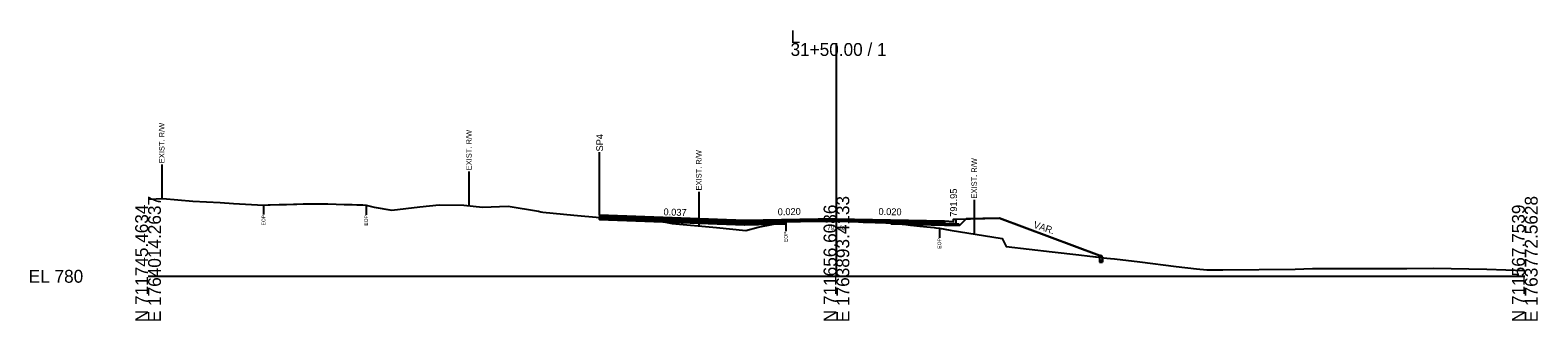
# Model space of a CAD drawing. Extents: x -26 to 5303, y -10 to 9578.
# Drawn here: x 1974.3 to 2302.8, y 1490.3 to 1553.6 of the extents above; entities that cross this region are included whole.
import ezdxf

# ---------------------------------------------------------------- set-up
doc = ezdxf.new("R2010")
doc.units = 0
for name, color, linetype in [('Default', 7, 'Continuous'), ('Exist CMT Pavement', 7, 'Continuous'), ('Exist Cross Section Cell', 7, 'Continuous'), ('Exist XS Ground Line', 7, 'Continuous'), ('Old_Level_10', 7, 'Continuous'), ('Old_Level_3', 7, 'Continuous'), ('Prop CMT Conc Surface', 7, 'Continuous'), ('Prop CMT Concrete Structures', 7, 'Continuous'), ('Prop CMT Pvmt Course 1', 7, 'Continuous'), ('Prop CMT Pvmt Course 1 CG', 7, 'Continuous'), ('Prop CMT Pvmt Course 2', 7, 'Continuous'), ('Prop CMT Pvmt Course 3', 7, 'Continuous'), ('Prop CMT Pvmt Surface', 7, 'Continuous'), ('Prop CMT Slope Grass', 7, 'Continuous'), ('Prop CMT Subgrade Earthwork', 7, 'Continuous'), ('Prop XS Earthwork Shape', 7, 'Continuous'), ('Prop XS Hydro Elevations', 7, 'Continuous'), ('Prop XS SE Text', 7, 'Continuous'), ('Prop XS Shear Point Element', 7, 'Continuous'), ('Prop XS Side Slope Text', 7, 'Continuous'), ('Prop XS Wedging', 7, 'Continuous'), ('Typical Curb CELL', 7, 'Continuous')]:
    doc.layers.add(name, color=color, linetype=linetype)

msp = doc.modelspace()

# ---------------------------------------------------------------- linework, layer by layer
at = {"layer": 'Exist CMT Pavement'}
msp.add_lwpolyline([(2138.95, 1511.9), (2140.27, 1511.94), (2141.07, 1511.96), (2142.16, 1511.96), (2142.86, 1511.97), (2143.38, 1511.98), (2144.65, 1512), (2146.74, 1512), (2149.58, 1512.03), (2150, 1512.02), (2150.74, 1512.02), (2152.68, 1511.94), (2153.59, 1511.9), (2154.83, 1511.85), (2155.38, 1511.83), (2155.79, 1511.81), (2158.46, 1511.73), (2159.05, 1511.71), (2160.74, 1511.66), (2161.89, 1511.55)], dxfattribs=at)
at = {"layer": 'Exist Cross Section Cell'}
for p, q in [((2150, 1500), (2150, 1550.77)), ((2000, 1500), (2150, 1500)), ((2150, 1500), (2300, 1500))]:
    msp.add_line(p, q, dxfattribs=at)
at = {"layer": 'Exist XS Ground Line'}
msp.add_lwpolyline([(2000, 1516.81), (2001.74, 1516.89), (2003.25, 1516.92), (2009.75, 1516.38), (2015.69, 1516.07), (2018.63, 1515.87), (2025.16, 1515.51), (2026.2, 1515.54), (2026.63, 1515.56), (2028.56, 1515.6), (2030.2, 1515.65), (2031.67, 1515.69), (2031.99, 1515.7), (2032.44, 1515.71), (2033.78, 1515.74), (2035.12, 1515.75), (2036.22, 1515.78), (2036.84, 1515.77), (2037.54, 1515.77), (2037.87, 1515.76), (2039.15, 1515.74), (2040.98, 1515.72), (2042.72, 1515.65), (2044.08, 1515.61), (2044.51, 1515.6), (2045.49, 1515.57), (2046.81, 1515.52), (2047.5, 1515.46), (2049.29, 1515.02), (2053.14, 1514.39), (2059.24, 1515.1), (2063.44, 1515.58), (2068.84, 1515.49), (2072.86, 1515.07), (2078.47, 1515.28), (2085.1, 1514.14), (2085.62, 1514.05), (2086, 1513.99), (2092.77, 1513.33), (2098.41, 1512.83), (2099.93, 1512.69), (2101.99, 1512.74), (2107.08, 1512.67), (2110.83, 1512.11), (2114.23, 1511.48), (2123.9, 1510.64), (2130.29, 1509.95), (2132.93, 1510.66), (2138.95, 1511.9), (2139.26, 1511.91), (2140.27, 1511.94), (2142.16, 1511.96), (2142.86, 1511.97), (2143.38, 1511.98), (2144.65, 1512), (2146.74, 1512), (2149.58, 1512.03), (2150, 1512.02), (2150.74, 1512.02), (2152.68, 1511.94), (2153.59, 1511.9), (2154.83, 1511.85), (2155.38, 1511.83), (2155.79, 1511.81), (2158.46, 1511.73), (2159.05, 1511.71), (2160.74, 1511.66), (2161.89, 1511.55), (2162.53, 1511.54), (2163.27, 1511.48), (2165.1, 1511.3), (2166.11, 1511.16), (2167.49, 1511.01), (2167.9, 1510.97), (2168.2, 1510.93), (2169.69, 1510.77), (2171.3, 1510.61), (2171.68, 1510.56), (2172.43, 1510.44), (2174.76, 1510.07), (2186.11, 1508.23), (2186.96, 1506.47), (2197.03, 1505.35), (2202.79, 1504.68), (2205.19, 1504.41), (2208.9, 1503.93), (2209.72, 1503.86), (2210.59, 1503.81), (2216.11, 1503.11), (2224.05, 1502.1), (2228.44, 1501.59), (2230.69, 1501.4), (2234.2, 1501.41), (2249.97, 1501.52), (2253.75, 1501.68), (2263.02, 1501.67), (2274.28, 1501.68), (2280, 1501.75), (2291.73, 1501.56), (2300, 1501.25)], dxfattribs=at)
at = {"layer": 'Old_Level_10'}
for p, q in [((2002.98, 1524.32), (2002.98, 1516.92)), ((2069.92, 1522.78), (2069.92, 1515.38)), ((2120.01, 1518.38), (2120.01, 1510.98)), ((2025.16, 1515.51), (2025.16, 1513.46)), ((2047.5, 1515.46), (2047.5, 1513.41)), ((2180.01, 1516.62), (2180.01, 1509.22)), ((2138.95, 1511.9), (2138.95, 1509.85)), ((2172.43, 1510.44), (2172.43, 1508.39))]:
    msp.add_line(p, q, dxfattribs=at)
at = {"layer": 'Prop CMT Conc Surface'}
for points in [[(2173.52, 1512.07), (2175.52, 1511.95)], [(2175.52, 1511.95), (2175.52, 1512.45), (2176.02, 1512.45)]]:
    msp.add_lwpolyline(points, dxfattribs=at)
at = {"layer": 'Prop CMT Concrete Structures'}
for points in [[(2173.52, 1512.07), (2175.52, 1511.95), (2175.52, 1512.45), (2176.02, 1512.45)], [(2176.02, 1512.45), (2176.02, 1511.44), (2173.52, 1511.49)], [(2173.52, 1511.49), (2173.52, 1512.07)]]:
    msp.add_lwpolyline(points, dxfattribs=at)
at = {"layer": 'Prop CMT Pvmt Course 1'}
for points in [[(2150, 1512.54), (2130.07, 1512.15)], [(2130.07, 1511.9), (2138.95, 1512.07)], [(2138.95, 1512.07), (2150, 1512.29)], [(2138.95, 1512.07), (2138.95, 1512.07)], [(2150, 1512.29), (2150, 1512.54)], [(2150, 1512.54), (2173.52, 1512.07)], [(2150, 1512.29), (2150, 1512.29), (2150, 1512.29)], [(2161.89, 1512.06), (2150, 1512.29)], [(2173.52, 1511.82), (2161.89, 1512.06)], [(2161.89, 1512.06), (2161.89, 1512.06)], [(2173.52, 1512.07), (2173.52, 1511.82)]]:
    msp.add_lwpolyline(points, dxfattribs=at)
at = {"layer": 'Prop CMT Pvmt Course 1 CG'}
for points in [[(2173.52, 1511.49), (2176.52, 1511.43), (2176.86, 1511.09)], [(2173.52, 1511.16), (2173.52, 1511.49)], [(2176.86, 1511.09), (2173.52, 1511.16)]]:
    msp.add_lwpolyline(points, dxfattribs=at)
at = {"layer": 'Prop CMT Pvmt Course 2'}
for p, q in [((2098.35, 1512.72), (2130.07, 1511.56)), ((2130.07, 1511.9), (2098.36, 1513.05))]:
    msp.add_line(p, q, dxfattribs=at)
for points in [[(2098.36, 1513.05), (2098.35, 1512.72)], [(2138.95, 1512.07), (2130.07, 1511.9)], [(2130.07, 1511.56), (2138.95, 1511.74)], [(2138.95, 1511.74), (2138.95, 1512.07)], [(2161.89, 1511.72), (2161.89, 1512.06)], [(2161.89, 1512.06), (2173.52, 1511.82)], [(2173.52, 1511.49), (2161.89, 1511.72)], [(2173.52, 1511.82), (2173.52, 1511.49)]]:
    msp.add_lwpolyline(points, dxfattribs=at)
at = {"layer": 'Prop CMT Pvmt Course 3'}
for p, q in [((2098.34, 1512.39), (2130.07, 1511.23)), ((2130.07, 1511.56), (2098.35, 1512.72))]:
    msp.add_line(p, q, dxfattribs=at)
for points in [[(2098.35, 1512.72), (2098.34, 1512.39)], [(2138.95, 1511.74), (2130.07, 1511.56)], [(2130.07, 1511.23), (2138.95, 1511.41)], [(2138.95, 1511.41), (2138.95, 1511.74)], [(2161.89, 1511.72), (2173.52, 1511.49)], [(2161.89, 1511.39), (2161.89, 1511.72)], [(2173.52, 1511.16), (2161.89, 1511.39)], [(2173.52, 1511.49), (2173.52, 1511.16)]]:
    msp.add_lwpolyline(points, dxfattribs=at)
at = {"layer": 'Prop CMT Pvmt Surface'}
for p, q in [((2098.37, 1513.3), (2098.35, 1512.83)), ((2130.07, 1512.15), (2098.37, 1513.3))]:
    msp.add_line(p, q, dxfattribs=at)
for points in [[(2150, 1512.54), (2130.07, 1512.15)], [(2150, 1512.54), (2173.52, 1512.07)]]:
    msp.add_lwpolyline(points, dxfattribs=at)
at = {"layer": 'Prop CMT Slope Grass'}
for p, q in [((2207.33, 1504.54), (2207.33, 1503.54)), ((2207.33, 1503.54), (2208, 1503.54)), ((2208, 1503.54), (2208, 1504.05))]:
    msp.add_line(p, q, dxfattribs=at)
msp.add_lwpolyline([(2176.02, 1512.45), (2185.52, 1512.64), (2207.33, 1504.54)], dxfattribs=at)
at = {"layer": 'Prop CMT Subgrade Earthwork'}
for p, q in [((2098.34, 1512.39), (2098.35, 1512.83)), ((2130.07, 1511.23), (2098.34, 1512.39)), ((2138.95, 1511.9), (2138.95, 1511.41)), ((2161.89, 1511.39), (2161.89, 1511.55))]:
    msp.add_line(p, q, dxfattribs=at)
for points in [[(2138.95, 1511.41), (2130.07, 1511.23)], [(2161.89, 1511.39), (2173.52, 1511.16)], [(2173.52, 1511.16), (2176.86, 1511.09), (2178.27, 1512.5)]]:
    msp.add_lwpolyline(points, dxfattribs=at)
at = {"layer": 'Prop XS Earthwork Shape'}
for points in [[(2101.99, 1512.74), (2107.08, 1512.67), (2110.83, 1512.11), (2112.03, 1511.89), (2098.34, 1512.39), (2098.35, 1512.83), (2098.41, 1512.83), (2099.93, 1512.69)], [(2098.34, 1512.39), (2098.35, 1512.83), (2098.41, 1512.83), (2099.93, 1512.69), (2101.99, 1512.74), (2107.08, 1512.67), (2110.83, 1512.11), (2112.03, 1511.89)], [(2136.3, 1511.35), (2130.07, 1511.23), (2112.03, 1511.89), (2114.23, 1511.48), (2123.9, 1510.64), (2130.29, 1509.95), (2132.93, 1510.66)], [(2132.93, 1510.66), (2136.3, 1511.35), (2130.07, 1511.23), (2112.03, 1511.89), (2114.23, 1511.48), (2123.9, 1510.64), (2130.29, 1509.95)], [(2138.95, 1511.41), (2136.3, 1511.35), (2138.95, 1511.9)], [(2161.89, 1511.39), (2164.77, 1511.33), (2164.32, 1511.38), (2163.27, 1511.48), (2162.53, 1511.54), (2161.89, 1511.55)], [(2161.89, 1511.55), (2162.53, 1511.54), (2163.27, 1511.48), (2164.32, 1511.38), (2164.77, 1511.33), (2161.89, 1511.39)], [(2167.9, 1510.97), (2168.2, 1510.93), (2169.69, 1510.77), (2171.3, 1510.61), (2171.68, 1510.56), (2172.43, 1510.44), (2174.76, 1510.07), (2186.11, 1508.23), (2186.96, 1506.47), (2197.03, 1505.35), (2202.79, 1504.68), (2205.19, 1504.41), (2207.33, 1504.13), (2207.33, 1504.54), (2185.52, 1512.64), (2178.27, 1512.5), (2176.86, 1511.09), (2173.52, 1511.16), (2164.77, 1511.33), (2165.1, 1511.3), (2166.11, 1511.16), (2167.49, 1511.01)], [(2186.96, 1506.47), (2197.03, 1505.35), (2202.79, 1504.68), (2205.19, 1504.41), (2207.33, 1504.13), (2207.33, 1504.54), (2185.52, 1512.64), (2178.27, 1512.5), (2176.86, 1511.09), (2173.52, 1511.16), (2164.77, 1511.33), (2165.1, 1511.3), (2166.11, 1511.16), (2167.49, 1511.01), (2167.9, 1510.97), (2168.2, 1510.93), (2169.69, 1510.77), (2171.3, 1510.61), (2171.68, 1510.56), (2172.43, 1510.44), (2174.76, 1510.07), (2186.11, 1508.23)], [(2208, 1503.54), (2208, 1504.05), (2207.33, 1504.13), (2207.33, 1503.54)]]:
    msp.add_lwpolyline(points, close=True, dxfattribs=at)
at = {"layer": 'Prop XS Shear Point Element'}
for p, q in [((2098.37, 1513.3), (2098.37, 1527)), ((2098.34, 1512.39), (2130, 1511.23))]:
    msp.add_line(p, q, dxfattribs=at)
at = {"layer": 'Prop XS Wedging'}
for points in [[(2138.95, 1511.9), (2138.95, 1512.07), (2139.26, 1512.08), (2140.27, 1512.1), (2141.07, 1512.12), (2142.16, 1512.14), (2142.86, 1512.15), (2143.38, 1512.16), (2144.65, 1512.19), (2146.74, 1512.23), (2149.58, 1512.29), (2150, 1512.3), (2150.74, 1512.28), (2152.68, 1512.24), (2153.59, 1512.22), (2154.83, 1512.2), (2155.38, 1512.19), (2155.79, 1512.18), (2158.46, 1512.13), (2159.05, 1512.11), (2160.74, 1512.08), (2161.89, 1512.06), (2161.89, 1511.55), (2160.74, 1511.66), (2159.05, 1511.71), (2158.46, 1511.73), (2155.79, 1511.82), (2155.38, 1511.83), (2154.83, 1511.85), (2153.59, 1511.9), (2152.68, 1511.94), (2150.74, 1512.02), (2150, 1512.02), (2149.58, 1512.03), (2146.74, 1512), (2144.65, 1512), (2143.38, 1511.98), (2142.86, 1511.97), (2142.16, 1511.96), (2141.07, 1511.96), (2140.27, 1511.94), (2139.26, 1511.91)], [(2145.51, 1512), (2145.72, 1512.21), (2146.74, 1512.23), (2149.58, 1512.29), (2150, 1512.3), (2150.74, 1512.28), (2152.68, 1512.24), (2153.59, 1512.22), (2154.83, 1512.2), (2155.38, 1512.19), (2155.79, 1512.18), (2158.46, 1512.13), (2159.05, 1512.11), (2160.74, 1512.08), (2161.89, 1512.06), (2161.89, 1511.55), (2160.74, 1511.66), (2159.05, 1511.71), (2158.46, 1511.73), (2155.79, 1511.82), (2155.38, 1511.83), (2154.83, 1511.85), (2153.59, 1511.9), (2152.68, 1511.94), (2150.74, 1512.02), (2150, 1512.02), (2149.58, 1512.03), (2146.74, 1512)]]:
    msp.add_lwpolyline(points, close=True, dxfattribs=at)
at = {"layer": 'Typical Curb CELL'}
for p, q in [((2207.33, 1504.54), (2207.53, 1504.54)), ((2207.33, 1504.54), (2207.33, 1503.54)), ((2207.33, 1503.55), (2207.33, 1503.04)), ((2207.33, 1503.54), (2208, 1503.54)), ((2207.33, 1503.04), (2208, 1503.04)), ((2208, 1504.13), (2207.65, 1504.49)), ((2208, 1504.13), (2208, 1503.54)), ((2208, 1503.55), (2208, 1503.04))]:
    msp.add_line(p, q, dxfattribs=at)
msp.add_arc((2207.53, 1504.38), 0.167, 43.9997, 90, dxfattribs=at)

# ---------------------------------------------------------------- texts
at = {"layer": 'Default'}
msp.add_text('-', height=0.0001, dxfattribs=at).set_placement((2000, 1500))
at = {"layer": 'Exist Cross Section Cell'}
for s, p in [('31+50.00 / 1', (2140, 1547.97)), ('L', (2140, 1550.77)), ('EL 780', (1974, 1498.6))]:
    msp.add_text(s, height=2.8, dxfattribs=at).set_placement(p)
for s, p in [('N 711745.4634', (2000, 1490)), ('E 1764014.2637', (2002.8, 1490)), ('N 711656.6086', (2150, 1490)), ('E 1763893.4133', (2152.8, 1490)), ('N 711567.7539', (2300, 1490)), ('E 1763772.5628', (2302.8, 1490))]:
    msp.add_text(s, height=2.8, rotation=90, dxfattribs=at).set_placement(p)
at = {"layer": 'Old_Level_10'}
for s, height, p in [('EXIST. R/W', 1.181, (2003.58, 1524.62)), ('EXIST. R/W', 1.181, (2070.51, 1523.08)), ('EXIST. R/W', 1.181, (2120.6, 1518.68)), ('EXIST. R/W', 1.181, (2180.6, 1516.93)), ('EOP', 0.787, (2025.56, 1511.06)), ('EOP', 0.787, (2047.9, 1511.01)), ('EOP', 0.787, (2139.35, 1507.45)), ('EOP', 0.787, (2172.83, 1506))]:
    msp.add_text(s, height=height, rotation=90, dxfattribs=at).set_placement(p)
at = {"layer": 'Old_Level_3'}
msp.add_text('792.02', height=1, dxfattribs=at).set_placement((2147.96, 1510.02))
at = {"layer": 'Prop XS Hydro Elevations'}
msp.add_text('791.95', height=1.5, rotation=90, dxfattribs=at).set_placement((2176.27, 1512.95))
at = {"layer": 'Prop XS SE Text'}
for s, rotation, p in [('0.037', 357.9063, (2112.3, 1513.29)), ('0.020', 1.1458, (2137.22, 1513.27)), ('0.020', 358.8542, (2159.16, 1513.36))]:
    msp.add_text(s, height=1.5, rotation=rotation, dxfattribs=at).set_placement(p)
at = {"layer": 'Prop XS Shear Point Element'}
msp.add_text('SP4', height=1.5, rotation=90, dxfattribs=at).set_placement((2099.15, 1527.17))
at = {"layer": 'Prop XS Side Slope Text'}
msp.add_text('VAR.', height=1.5, rotation=341.5651, dxfattribs=at).set_placement((2192.8, 1510.61))

doc.saveas('drawing.dxf')
